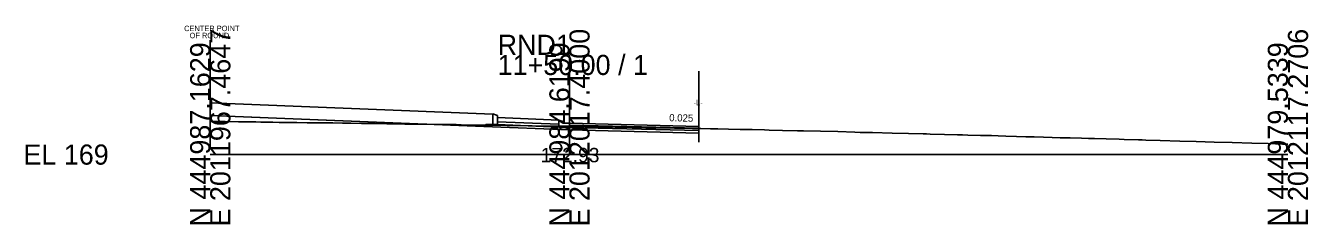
# Model space of a CAD drawing. Extents: x -26 to 153, y -10 to 6017.
# Drawn here: x -25.7 to 152.8, y 2990.3 to 3017.9 of the extents above; entities that cross this region are included whole.
import ezdxf

# ---------------------------------------------------------------- set-up
doc = ezdxf.new("R2010")
doc.units = 0
for name, color, linetype in [('Exist Cross Section Cell', 7, 'Continuous'), ('Exist XS Ground Line', 7, 'Continuous'), ('Prop CMT Conc Surface', 7, 'Continuous'), ('Prop CMT Concrete Structures', 7, 'Continuous'), ('Prop CMT Pvmt Course 1', 7, 'Continuous'), ('Prop CMT Pvmt Course 1 CG', 7, 'Continuous'), ('Prop CMT Pvmt Course 2', 7, 'Continuous'), ('Prop CMT Pvmt Course 3', 7, 'Continuous'), ('Prop CMT Pvmt Surface', 7, 'Continuous'), ('Prop CMT Shear Line', 7, 'Continuous'), ('Prop CMT Shear Line Text', 7, 'Continuous'), ('Prop CMT Slope Grass', 7, 'Continuous'), ('Prop CMT Subgrade Earthwork', 7, 'Continuous'), ('Prop XS Earthwork Shape', 7, 'Continuous'), ('Prop XS SE Text', 7, 'Continuous'), ('Scratch_Level_1', 7, 'Continuous')]:
    doc.layers.add(name, color=color, linetype=linetype)

msp = doc.modelspace()

# ---------------------------------------------------------------- linework, layer by layer
at = {"layer": 'Exist Cross Section Cell'}
for p, q in [((50, 3000), (50, 3013.86)), ((0, 3000), (50, 3000)), ((50, 3000), (150, 3000))]:
    msp.add_line(p, q, dxfattribs=at)
at = {"layer": 'Exist XS Ground Line'}
msp.add_lwpolyline([(0, 3004.62), (1.56, 3004.6), (2.06, 3004.59), (3.95, 3004.56), (4.56, 3004.55), (6.34, 3004.53), (7.06, 3004.52), (8.71, 3004.49), (9.57, 3004.48), (11.09, 3004.47), (12.07, 3004.45), (13.48, 3004.43), (14.58, 3004.42), (15.78, 3004.4), (17.07, 3004.39), (18.41, 3004.37), (19.58, 3004.36), (21.06, 3004.34), (22.08, 3004.32), (23.01, 3004.31), (24.59, 3004.29), (26.34, 3004.26), (27.09, 3004.25), (28.97, 3004.23), (29.59, 3004.22), (30.15, 3004.21), (32.1, 3004.18), (34.25, 3004.16), (34.6, 3004.15), (34.92, 3004.14), (37.3, 3004.11), (39.6, 3004.08), (41.32, 3004.05), (42.11, 3004.04), (44.79, 3004), (47.12, 3003.97), (49.21, 3003.94), (49.61, 3003.93), (50.05, 3003.93), (52.12, 3003.89), (53.98, 3003.85), (54.63, 3003.84), (56.36, 3003.81), (57.12, 3003.8), (58.74, 3003.77), (59.63, 3003.75), (60.62, 3003.74), (62.13, 3003.71), (63.25, 3003.7), (64.64, 3003.68), (65.88, 3003.66), (67.14, 3003.63), (68.27, 3003.61), (69.65, 3003.59), (70.66, 3003.57), (72.15, 3003.54), (73.78, 3003.5), (74.64, 3003.48), (75.42, 3003.47), (77.15, 3003.43), (77.8, 3003.41), (79.65, 3003.37), (81.72, 3003.32), (82.16, 3003.31), (82.56, 3003.3), (84.94, 3003.26), (87.33, 3003.2), (89.71, 3003.11), (90.45, 3003.09), (92.17, 3003.05), (94.9, 3002.99), (97.18, 3002.93), (99.23, 3002.88), (99.68, 3002.87), (100.18, 3002.86), (102.18, 3002.81), (104, 3002.76), (104.69, 3002.74), (105.45, 3002.72), (107.19, 3002.67), (108.76, 3002.63), (109.69, 3002.6), (110.72, 3002.57), (112.2, 3002.53), (113.53, 3002.49), (114.7, 3002.45), (115.99, 3002.42), (117.2, 3002.38), (118.29, 3002.35), (119.71, 3002.31), (121.27, 3002.27), (122.22, 3002.24), (123.07, 3002.22), (124.71, 3002.17), (126.53, 3002.12), (127.22, 3002.1), (129.19, 3002.04), (129.72, 3002.03), (130.2, 3002.02), (132.22, 3001.96), (134.97, 3001.87), (137.23, 3001.8), (139.73, 3001.74), (142.24, 3001.67), (144.99, 3001.59), (147.25, 3001.52), (149.26, 3001.46), (150, 3001.44)], dxfattribs=at)
at = {"layer": 'Prop CMT Conc Surface'}
for points in [[(40, 3005.32), (39.96, 3005.43), (39.85, 3005.47), (39.34, 3005.66)], [(40, 3005.16), (40, 3005.32)], [(50, 3004.36), (49.25, 3004.38), (49.25, 3004.55), (48.5, 3004.8)]]:
    msp.add_lwpolyline(points, dxfattribs=at)
at = {"layer": 'Prop CMT Concrete Structures'}
for points in [[(40, 3005.32), (39.96, 3005.43), (39.85, 3005.47), (39.34, 3005.66)], [(39.34, 3005.66), (39.34, 3004.16)], [(40, 3005.16), (40, 3005.32)], [(40, 3004.16), (40, 3005.16)], [(40, 3005.16), (40, 3004.57)], [(48.5, 3004.8), (40, 3005.14)], [(50, 3004.36), (49.25, 3004.38), (49.25, 3004.55), (48.5, 3004.8)], [(48.5, 3004.8), (48.5, 3003.82)], [(48.5, 3004.21), (48.5, 3004.8)], [(39.34, 3004.16), (40, 3004.16)], [(40, 3004.55), (48.5, 3004.21)], [(48.5, 3003.82), (50, 3003.78)], [(50, 3003.78), (50, 3004.36)]]:
    msp.add_lwpolyline(points, dxfattribs=at)
at = {"layer": 'Prop CMT Pvmt Course 1'}
for points in [[(50, 3004.36), (68, 3003.91)], [(50, 3004.11), (50, 3004.36)], [(68, 3003.66), (50, 3004.11)], [(68, 3003.91), (68, 3003.66)]]:
    msp.add_lwpolyline(points, dxfattribs=at)
msp.add_lwpolyline([(50, 3004.11), (50, 3004.24), (50, 3004.24), (50, 3004.11)], close=True, dxfattribs=at)
at = {"layer": 'Prop CMT Pvmt Course 1 CG'}
for points in [[(50, 3003.44), (50, 3003.78)], [(68, 3002.99), (68, 3003.33)]]:
    msp.add_lwpolyline(points, dxfattribs=at)
at = {"layer": 'Prop CMT Pvmt Course 2'}
for points in [[(50, 3003.78), (50, 3004.11)], [(50, 3004.11), (68, 3003.66)], [(68, 3003.33), (50, 3003.78)], [(68, 3003.66), (68, 3003.33)]]:
    msp.add_lwpolyline(points, dxfattribs=at)
at = {"layer": 'Prop CMT Pvmt Course 3'}
for points in [[(40, 3004.16), (48.5, 3003.82)], [(50, 3003.78), (68, 3003.33)], [(50, 3003.44), (50, 3003.78)], [(68, 3002.99), (50, 3003.44)], [(68, 3003.33), (68, 3002.99)]]:
    msp.add_lwpolyline(points, dxfattribs=at)
at = {"layer": 'Prop CMT Pvmt Surface'}
msp.add_lwpolyline([(50, 3004.36), (68, 3003.91)], dxfattribs=at)
at = {"layer": 'Prop CMT Shear Line'}
for p, q in [((0, 3000.9), (0, 3015.9)), ((68, 3001.74), (68, 3006.75))]:
    msp.add_line(p, q, dxfattribs=at)
at = {"layer": 'Prop CMT Slope Grass'}
for p, q in [((39.34, 3005.64), (0, 3007.21)), ((38.06, 3003.92), (0, 3005.44))]:
    msp.add_line(p, q, dxfattribs=at)
at = {"layer": 'Prop CMT Subgrade Earthwork'}
for p, q in [((0, 3007.21), (0, 3004.62)), ((38.34, 3004.2), (38.06, 3003.92)), ((68, 3003.91), (68, 3003.62)), ((68, 3002.99), (68, 3003.62))]:
    msp.add_line(p, q, dxfattribs=at)
for points in [[(38.06, 3003.92), (50, 3003.44)], [(38.34, 3004.2), (39.34, 3004.16)], [(50, 3003.44), (68, 3002.99)]]:
    msp.add_lwpolyline(points, dxfattribs=at)
at = {"layer": 'Prop XS Earthwork Shape'}
for points in [[(31.19, 3004.2), (0, 3005.44), (0, 3004.62), (1.56, 3004.6), (2.06, 3004.59), (3.95, 3004.56), (4.56, 3004.55), (6.34, 3004.53), (7.06, 3004.52), (8.71, 3004.49), (9.57, 3004.48), (11.09, 3004.47), (12.07, 3004.45), (13.48, 3004.43), (14.58, 3004.42), (15.78, 3004.4), (17.07, 3004.39), (18.41, 3004.37), (19.58, 3004.36), (21.06, 3004.34), (22.08, 3004.32), (23.01, 3004.31), (24.59, 3004.29), (26.34, 3004.26), (27.09, 3004.25), (28.97, 3004.23), (29.59, 3004.22), (30.15, 3004.21)], [(31.19, 3004.2), (32.1, 3004.18), (34.25, 3004.16), (34.6, 3004.15), (34.92, 3004.14), (37.3, 3004.11), (38.23, 3004.09), (38.06, 3003.92)], [(48.5, 3003.82), (50, 3003.78), (50, 3003.93), (50.05, 3003.93), (52.12, 3003.89), (53.98, 3003.85), (54.63, 3003.84), (56.36, 3003.81), (57.12, 3003.8), (58.74, 3003.77), (59.63, 3003.75), (60.62, 3003.74), (62.13, 3003.71), (63.25, 3003.7), (64.64, 3003.68), (65.88, 3003.66), (67.14, 3003.63), (68, 3003.62), (68, 3002.99), (50, 3003.44), (38.06, 3003.92), (38.23, 3004.09), (39.6, 3004.08), (41.32, 3004.05), (42.11, 3004.04), (44.79, 3004), (47.12, 3003.97), (48.5, 3003.95)], [(48.5, 3003.82), (50, 3003.78), (50, 3003.93), (49.61, 3003.93), (49.21, 3003.94), (48.5, 3003.95)]]:
    msp.add_lwpolyline(points, close=True, dxfattribs=at)
at = {"layer": 'Scratch_Level_1'}
msp.add_line((68, 3003.56), (68, 3011.58), dxfattribs=at)

# ---------------------------------------------------------------- texts
at = {"layer": 'Exist Cross Section Cell'}
for s, p in [('E 2011967.4647', (2.8, 2990)), ('E 2012017.4000', (52.8, 2990)), ('E 2012117.2706', (152.8, 2990)), ('N 444987.1629', (0, 2990)), ('N 444984.6199', (50, 2990)), ('N 444979.5339', (150, 2990))]:
    msp.add_text(s, height=2.8, rotation=90, dxfattribs=at).set_placement(p)
for s, p in [('RND1', (40, 3013.86)), ('11+50.00 / 1', (40, 3011.06)), ('EL 169', (-26, 2998.6))]:
    msp.add_text(s, height=2.8, dxfattribs=at).set_placement(p)
at = {"layer": 'Exist XS Ground Line'}
msp.add_text('172.93', height=2, dxfattribs=at).set_placement((45.99, 2998.93))
at = {"layer": 'Prop CMT Shear Line Text'}
for s, p in [('CENTER POINT', (-3.64, 3017.16)), ('OF ROUND', (-2.88, 3016.18)), ('-L-', (67.27, 3006.86))]:
    msp.add_text(s, height=0.75, dxfattribs=at).set_placement(p)
at = {"layer": 'Prop XS SE Text'}
msp.add_text('0.025', height=1, rotation=358.5613, dxfattribs=at).set_placement((63.87, 3004.64))

doc.saveas('drawing.dxf')
